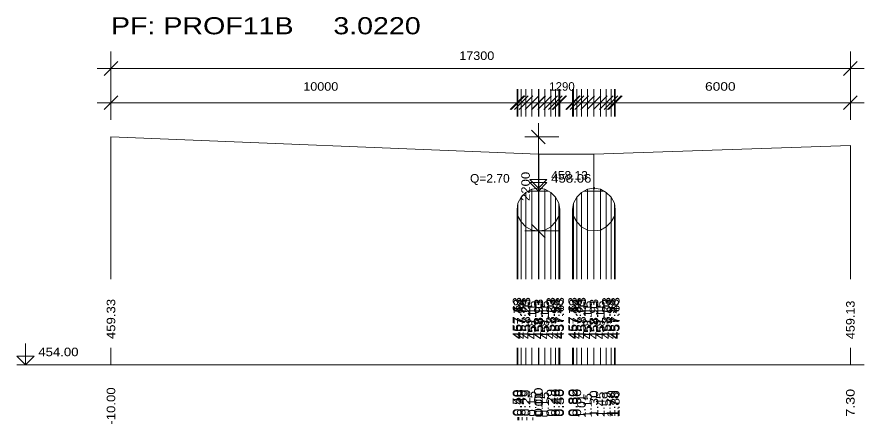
# Model space of a CAD drawing. Extents: x 7 to 442, y -393 to 441.
# Drawn here: x 409.84 to 429.66, y -199.42 to -189.9 of the extents above; entities that cross this region are included whole.
import ezdxf

# ---------------------------------------------------------------- set-up
doc = ezdxf.new("R2010")
doc.units = 0
doc.header["$LTSCALE"] = 0.08
doc.header["$PDMODE"] = 32
doc.header["$PDSIZE"] = 0.04
doc.layers.add('7', color=7, linetype='Continuous', lineweight=13)

msp = doc.modelspace()

# ---------------------------------------------------------------- linework, layer by layer
at = {"layer": '7'}
for p, q in [((412.038, -192.304), (412.038, -190.704)), ((429.338, -192.304), (429.338, -190.704)), ((411.878, -191.264), (412.198, -190.944)), ((429.178, -191.264), (429.498, -190.944)), ((411.718, -191.104), (429.658, -191.104)), ((412.038, -192.224), (412.038, -191.584)), ((421.538, -192.224), (421.538, -191.584)), ((421.558, -192.224), (421.558, -191.584)), ((421.558, -192.224), (421.558, -191.584)), ((421.638, -192.224), (421.638, -191.584)), ((421.638, -192.224), (421.638, -191.584)), ((421.748, -192.224), (421.748, -191.584)), ((421.748, -192.224), (421.748, -191.584)), ((421.888, -192.224), (421.888, -191.584)), ((421.888, -192.224), (421.888, -191.584)), ((422.038, -192.224), (422.038, -191.584)), ((422.038, -192.224), (422.038, -191.584)), ((422.038, -192.224), (422.038, -191.584)), ((422.048, -192.224), (422.048, -191.584)), ((422.048, -192.224), (422.048, -191.584)), ((422.188, -192.224), (422.188, -191.584)), ((422.188, -192.224), (422.188, -191.584)), ((422.328, -192.224), (422.328, -191.584)), ((422.328, -192.224), (422.328, -191.584)), ((422.438, -192.224), (422.438, -191.584)), ((422.438, -192.224), (422.438, -191.584)), ((422.518, -192.224), (422.518, -191.584)), ((422.518, -192.224), (422.518, -191.584)), ((422.538, -192.224), (422.538, -191.584)), ((422.838, -192.224), (422.838, -191.584)), ((422.858, -192.224), (422.858, -191.584)), ((422.858, -192.224), (422.858, -191.584)), ((422.938, -192.224), (422.938, -191.584)), ((422.938, -192.224), (422.938, -191.584)), ((423.048, -192.224), (423.048, -191.584)), ((423.048, -192.224), (423.048, -191.584)), ((423.188, -192.224), (423.188, -191.584)), ((423.188, -192.224), (423.188, -191.584)), ((423.338, -192.224), (423.338, -191.584)), ((423.338, -192.224), (423.338, -191.584)), ((423.338, -192.224), (423.338, -191.584)), ((423.338, -192.224), (423.338, -191.584)), ((423.338, -192.224), (423.338, -191.584)), ((423.488, -192.224), (423.488, -191.584)), ((423.488, -192.224), (423.488, -191.584)), ((423.628, -192.224), (423.628, -191.584)), ((423.628, -192.224), (423.628, -191.584)), ((423.738, -192.224), (423.738, -191.584)), ((423.738, -192.224), (423.738, -191.584)), ((423.818, -192.224), (423.818, -191.584)), ((423.818, -192.224), (423.818, -191.584)), ((423.838, -192.224), (423.838, -191.584)), ((429.338, -192.224), (429.338, -191.584)), ((411.878, -192.064), (412.198, -191.744)), ((421.378, -192.064), (421.698, -191.744)), ((421.398, -192.064), (421.718, -191.744)), ((421.398, -192.064), (421.718, -191.744)), ((421.478, -192.064), (421.798, -191.744)), ((421.478, -192.064), (421.798, -191.744)), ((421.588, -192.064), (421.908, -191.744)), ((421.588, -192.064), (421.908, -191.744)), ((421.728, -192.064), (422.048, -191.744)), ((421.728, -192.064), (422.048, -191.744)), ((421.878, -192.064), (422.198, -191.744)), ((421.878, -192.064), (422.198, -191.744)), ((421.878, -192.064), (422.198, -191.744)), ((421.888, -192.064), (422.208, -191.744)), ((421.888, -192.064), (422.208, -191.744)), ((422.028, -192.064), (422.348, -191.744)), ((422.028, -192.064), (422.348, -191.744)), ((422.168, -192.064), (422.488, -191.744)), ((422.168, -192.064), (422.488, -191.744)), ((422.278, -192.064), (422.598, -191.744)), ((422.278, -192.064), (422.598, -191.744)), ((422.358, -192.064), (422.678, -191.744)), ((422.358, -192.064), (422.678, -191.744)), ((422.378, -192.064), (422.698, -191.744)), ((422.678, -192.064), (422.998, -191.744)), ((422.698, -192.064), (423.018, -191.744)), ((422.698, -192.064), (423.018, -191.744)), ((422.778, -192.064), (423.098, -191.744)), ((422.778, -192.064), (423.098, -191.744)), ((422.888, -192.064), (423.208, -191.744)), ((422.888, -192.064), (423.208, -191.744)), ((423.028, -192.064), (423.348, -191.744)), ((423.028, -192.064), (423.348, -191.744)), ((423.178, -192.064), (423.498, -191.744)), ((423.178, -192.064), (423.498, -191.744)), ((423.178, -192.064), (423.498, -191.744)), ((423.178, -192.064), (423.498, -191.744)), ((423.178, -192.064), (423.498, -191.744)), ((423.328, -192.064), (423.648, -191.744)), ((423.328, -192.064), (423.648, -191.744)), ((423.468, -192.064), (423.788, -191.744)), ((423.468, -192.064), (423.788, -191.744)), ((423.578, -192.064), (423.898, -191.744)), ((423.578, -192.064), (423.898, -191.744)), ((423.658, -192.064), (423.978, -191.744)), ((423.658, -192.064), (423.978, -191.744)), ((423.678, -192.064), (423.998, -191.744)), ((429.178, -192.064), (429.498, -191.744)), ((411.718, -191.904), (429.658, -191.904)), ((422.038, -195.064), (422.038, -192.384)), ((422.198, -192.864), (421.878, -192.544)), ((412.038, -196.034), (412.038, -192.704)), ((421.718, -192.704), (422.518, -192.704)), ((429.338, -196.034), (429.338, -192.904)), ((422.038, -196.034), (422.038, -193.104)), ((422.048, -196.034), (422.048, -193.104)), ((423.338, -196.034), (423.338, -193.104)), ((423.338, -196.034), (423.338, -193.104)), ((421.748, -196.034), (421.748, -194.004)), ((421.801, -193.974), (422.275, -193.974)), ((421.888, -196.034), (421.888, -193.924)), ((422.038, -196.034), (422.038, -193.904)), ((422.038, -193.904), (422.048, -193.904)), ((422.048, -196.034), (422.048, -193.904)), ((422.188, -196.034), (422.188, -193.924)), ((422.328, -196.034), (422.328, -194.004)), ((423.048, -196.034), (423.048, -194.004)), ((423.101, -193.974), (423.575, -193.974)), ((423.188, -196.034), (423.188, -193.924)), ((423.338, -196.034), (423.338, -193.904)), ((423.338, -196.034), (423.338, -193.904)), ((423.488, -196.034), (423.488, -193.924)), ((423.628, -196.034), (423.628, -194.004)), ((421.638, -196.034), (421.638, -194.114)), ((422.438, -196.034), (422.438, -194.114)), ((422.938, -196.034), (422.938, -194.114)), ((423.738, -196.034), (423.738, -194.114)), ((421.538, -196.034), (421.538, -194.404)), ((421.558, -196.034), (421.558, -194.254)), ((422.518, -196.034), (422.518, -194.254)), ((422.538, -196.034), (422.538, -194.404)), ((422.838, -196.034), (422.838, -194.404)), ((422.858, -196.034), (422.858, -194.254)), ((423.818, -196.034), (423.818, -194.254)), ((423.838, -196.034), (423.838, -194.404)), ((421.558, -196.034), (421.558, -194.554)), ((422.518, -196.034), (422.518, -194.554)), ((422.858, -196.034), (422.858, -194.554)), ((423.818, -196.034), (423.818, -194.554)), ((421.638, -196.034), (421.638, -194.694)), ((421.748, -196.034), (421.748, -194.804)), ((422.198, -195.064), (421.878, -194.744)), ((422.328, -196.034), (422.328, -194.804)), ((422.438, -196.034), (422.438, -194.694)), ((422.938, -196.034), (422.938, -194.694)), ((423.048, -196.034), (423.048, -194.804)), ((423.628, -196.034), (423.628, -194.804)), ((423.738, -196.034), (423.738, -194.694)), ((421.718, -194.904), (422.518, -194.904)), ((421.888, -196.034), (421.888, -194.884)), ((422.038, -196.034), (422.038, -194.904)), ((422.188, -196.034), (422.188, -194.884)), ((423.188, -196.034), (423.188, -194.884)), ((423.338, -196.034), (423.338, -194.904)), ((423.488, -196.034), (423.488, -194.884)), ((412.038, -198.034), (412.038, -197.634)), ((421.538, -198.034), (421.538, -197.634)), ((421.558, -198.034), (421.558, -197.634)), ((421.558, -198.034), (421.558, -197.634)), ((421.638, -198.034), (421.638, -197.634)), ((421.638, -198.034), (421.638, -197.634)), ((421.748, -198.034), (421.748, -197.634)), ((421.748, -198.034), (421.748, -197.634)), ((421.888, -198.034), (421.888, -197.634)), ((421.888, -198.034), (421.888, -197.634)), ((422.038, -198.034), (422.038, -197.634)), ((422.038, -198.034), (422.038, -197.634)), ((422.038, -198.034), (422.038, -197.634)), ((422.048, -198.034), (422.048, -197.634)), ((422.048, -198.034), (422.048, -197.634)), ((422.188, -198.034), (422.188, -197.634)), ((422.188, -198.034), (422.188, -197.634)), ((422.328, -198.034), (422.328, -197.634)), ((422.328, -198.034), (422.328, -197.634)), ((422.438, -198.034), (422.438, -197.634)), ((422.438, -198.034), (422.438, -197.634)), ((422.518, -198.034), (422.518, -197.634)), ((422.518, -198.034), (422.518, -197.634)), ((422.538, -198.034), (422.538, -197.634)), ((422.838, -198.034), (422.838, -197.634)), ((422.858, -198.034), (422.858, -197.634)), ((422.858, -198.034), (422.858, -197.634)), ((422.938, -198.034), (422.938, -197.634)), ((422.938, -198.034), (422.938, -197.634)), ((423.048, -198.034), (423.048, -197.634)), ((423.048, -198.034), (423.048, -197.634)), ((423.188, -198.034), (423.188, -197.634)), ((423.188, -198.034), (423.188, -197.634)), ((423.338, -198.034), (423.338, -197.634)), ((423.338, -198.034), (423.338, -197.634)), ((423.338, -198.034), (423.338, -197.634)), ((423.338, -198.034), (423.338, -197.634)), ((423.338, -198.034), (423.338, -197.634)), ((423.488, -198.034), (423.488, -197.634)), ((423.488, -198.034), (423.488, -197.634)), ((423.628, -198.034), (423.628, -197.634)), ((423.628, -198.034), (423.628, -197.634)), ((423.738, -198.034), (423.738, -197.634)), ((423.738, -198.034), (423.738, -197.634)), ((423.818, -198.034), (423.818, -197.634)), ((423.818, -198.034), (423.818, -197.634)), ((423.838, -198.034), (423.838, -197.634)), ((429.338, -198.034), (429.338, -197.634)), ((409.838, -198.034), (429.658, -198.034))]:
    msp.add_line(p, q, dxfattribs=at)
for points in [[(412.038, -192.704), (422.038, -193.104), (422.038, -193.904), (421.888, -193.924), (421.748, -194.004), (421.638, -194.114), (421.558, -194.254), (421.538, -194.404), (421.558, -194.554), (421.638, -194.694), (421.748, -194.804), (421.888, -194.884), (422.038, -194.904), (422.188, -194.884), (422.328, -194.804), (422.438, -194.694), (422.518, -194.554), (422.538, -194.404), (422.518, -194.254), (422.438, -194.114), (422.328, -194.004), (422.188, -193.924), (422.048, -193.904), (422.048, -193.104), (423.338, -193.104), (423.338, -193.904), (423.188, -193.924), (423.048, -194.004), (422.938, -194.114), (422.858, -194.254), (422.838, -194.404), (422.858, -194.554), (422.938, -194.694), (423.048, -194.804), (423.188, -194.884), (423.338, -194.904), (423.488, -194.884), (423.628, -194.804), (423.738, -194.694), (423.818, -194.554), (423.838, -194.404), (423.818, -194.254), (423.738, -194.114), (423.628, -194.004), (423.488, -193.924), (423.338, -193.904), (423.338, -193.104), (429.338, -192.904)], [(422.038, -193.404), (422.038, -193.904), (421.838, -193.704), (422.238, -193.704), (422.038, -193.904)], [(422.038, -193.474), (422.038, -193.974), (421.838, -193.774), (422.238, -193.774), (422.038, -193.974)], [(410.038, -197.534), (410.038, -198.034), (409.838, -197.834), (410.238, -197.834), (410.038, -198.034)]]:
    msp.add_lwpolyline(points, dxfattribs=at)
msp.add_point((423.338, -193.904), dxfattribs=at)

# ---------------------------------------------------------------- texts
for s, height, width, p in [('PF: PROF11B     3.0220', 0.4, 1.25, (412.038, -190.304)), ('17300', 0.2, 1.1, (420.188, -190.904)), ('10000', 0.2, 1.1, (416.538, -191.624)), ('6000', 0.2, 1.2, (425.938, -191.624)), ('Q=2.70', 0.2, 1.05, (420.438, -193.774)), ('458.13', 0.2, 1.05, (422.338, -193.704)), ('458.06', 0.2, 1.15, (422.338, -193.774)), ('454.00', 0.2, 1.15, (410.338, -197.834))]:
    msp.add_text(s, height=height, dxfattribs=dict(at, width=width)).set_placement(p)
msp.add_text('1290', height=0.2, dxfattribs=at).set_placement((422.293, -191.624))
for s, width, p in [('2200', 1.15, (421.838, -194.204)), ('459.33 ', 1.15, (412.138, -197.434)), ('457.63 ', 1.2, (421.638, -197.434)), ('457.78 ', 1.15, (421.658, -197.434)), ('457.48 ', 1.15, (421.658, -197.434)), ('457.34 ', 1.15, (421.738, -197.434)), ('457.92 ', 1.15, (421.738, -197.434)), ('458.03 ', 1.2, (421.848, -197.434)), ('457.23 ', 1.15, (421.848, -197.434)), ('457.15 ', 1.1, (421.988, -197.434)), ('458.93 ', 1.15, (422.138, -197.434)), ('458.13 ', 1.1, (422.138, -197.434)), ('457.13 ', 1.1, (422.138, -197.434)), ('458.93 ', 1.15, (422.148, -197.434)), ('458.13 ', 1.1, (422.148, -197.434)), ('457.15 ', 1.1, (422.288, -197.434)), ('458.03 ', 1.2, (422.428, -197.434)), ('457.23 ', 1.15, (422.428, -197.434)), ('457.34 ', 1.15, (422.538, -197.434)), ('457.92 ', 1.15, (422.538, -197.434)), ('457.48 ', 1.15, (422.618, -197.434)), ('457.78 ', 1.15, (422.618, -197.434)), ('457.63 ', 1.2, (422.638, -197.434)), ('457.63 ', 1.2, (422.938, -197.434)), ('457.78 ', 1.15, (422.958, -197.434)), ('457.48 ', 1.15, (422.958, -197.434)), ('457.34 ', 1.15, (423.038, -197.434)), ('457.92 ', 1.15, (423.038, -197.434)), ('458.03 ', 1.2, (423.148, -197.434)), ('457.23 ', 1.15, (423.148, -197.434)), ('457.15 ', 1.1, (423.288, -197.434)), ('458.93 ', 1.15, (423.438, -197.434)), ('458.93 ', 1.15, (423.438, -197.434)), ('458.13 ', 1.1, (423.438, -197.434)), ('457.13 ', 1.1, (423.438, -197.434)), ('458.13 ', 1.1, (423.438, -197.434)), ('457.15 ', 1.1, (423.588, -197.434)), ('458.03 ', 1.2, (423.728, -197.434)), ('457.23 ', 1.15, (423.728, -197.434)), ('457.34 ', 1.15, (423.838, -197.434)), ('457.92 ', 1.15, (423.838, -197.434)), ('457.48 ', 1.15, (423.918, -197.434)), ('457.78 ', 1.15, (423.918, -197.434)), ('457.63 ', 1.2, (423.938, -197.434)), ('459.13 ', 1.1, (429.438, -197.434)), ('-10.00 ', 1.15, (412.138, -199.434)), ('  0.00 ', 1.3, (422.138, -199.434)), ('  0.00 ', 1.3, (422.138, -199.434)), ('  0.00 ', 1.3, (422.138, -199.434)), (' -0.50 ', 1.2, (421.638, -199.434)), (' -0.48 ', 1.2, (421.658, -199.434)), (' -0.48 ', 1.2, (421.658, -199.434)), (' -0.40 ', 1.2, (421.738, -199.434)), (' -0.40 ', 1.2, (421.738, -199.434)), (' -0.29 ', 1.2, (421.848, -199.434)), (' -0.29 ', 1.2, (421.848, -199.434)), (' -0.15 ', 1.15, (421.988, -199.434)), (' -0.15 ', 1.15, (421.988, -199.434)), ('  0.01 ', 1.15, (422.148, -199.434)), ('  0.01 ', 1.15, (422.148, -199.434)), ('  0.15 ', 1.15, (422.288, -199.434)), ('  0.15 ', 1.15, (422.288, -199.434)), ('  0.29 ', 1.25, (422.428, -199.434)), ('  0.29 ', 1.25, (422.428, -199.434)), ('  0.40 ', 1.25, (422.538, -199.434)), ('  0.40 ', 1.25, (422.538, -199.434)), ('  0.48 ', 1.25, (422.618, -199.434)), ('  0.48 ', 1.25, (422.618, -199.434)), ('  0.50 ', 1.25, (422.638, -199.434)), ('  0.80 ', 1.25, (422.938, -199.434)), ('  0.82 ', 1.25, (422.958, -199.434)), ('  0.82 ', 1.25, (422.958, -199.434)), ('  0.90 ', 1.25, (423.038, -199.434)), ('  0.90 ', 1.25, (423.038, -199.434)), ('  1.01 ', 1.05, (423.148, -199.434)), ('  1.01 ', 1.05, (423.148, -199.434)), ('  1.15 ', 1.1, (423.288, -199.434)), ('  1.15 ', 1.1, (423.288, -199.434)), ('  1.30 ', 1.2, (423.438, -199.434)), ('  1.30 ', 1.2, (423.438, -199.434)), ('  1.30 ', 1.2, (423.438, -199.434)), ('  1.30 ', 1.2, (423.438, -199.434)), ('  1.30 ', 1.2, (423.438, -199.434)), ('  1.45 ', 1.15, (423.588, -199.434)), ('  1.45 ', 1.15, (423.588, -199.434)), ('  1.59 ', 1.15, (423.728, -199.434)), ('  1.59 ', 1.15, (423.728, -199.434)), ('  1.70 ', 1.2, (423.838, -199.434)), ('  1.70 ', 1.2, (423.838, -199.434)), ('  1.78 ', 1.15, (423.918, -199.434)), ('  1.78 ', 1.15, (423.918, -199.434)), ('  1.80 ', 1.2, (423.938, -199.434)), ('  7.30 ', 1.25, (429.438, -199.434))]:
    msp.add_text(s, height=0.2, rotation=90, dxfattribs=dict(at, width=width)).set_placement(p)
for p in [(421.988, -197.434), (422.288, -197.434), (423.288, -197.434), (423.588, -197.434)]:
    msp.add_text('458.11 ', height=0.2, rotation=90, dxfattribs=at).set_placement(p)

doc.saveas('drawing.dxf')
